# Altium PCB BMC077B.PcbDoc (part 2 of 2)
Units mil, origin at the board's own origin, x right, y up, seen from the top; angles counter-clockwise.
Board outline 3180 x 2450 mil, 4 copper layers (Top Layer, Signal Layer 1, Signal Layer 2, Bottom Layer), stack 61.2 mil thick; 102 components, 30 nets, 186 pads, 124 vias.
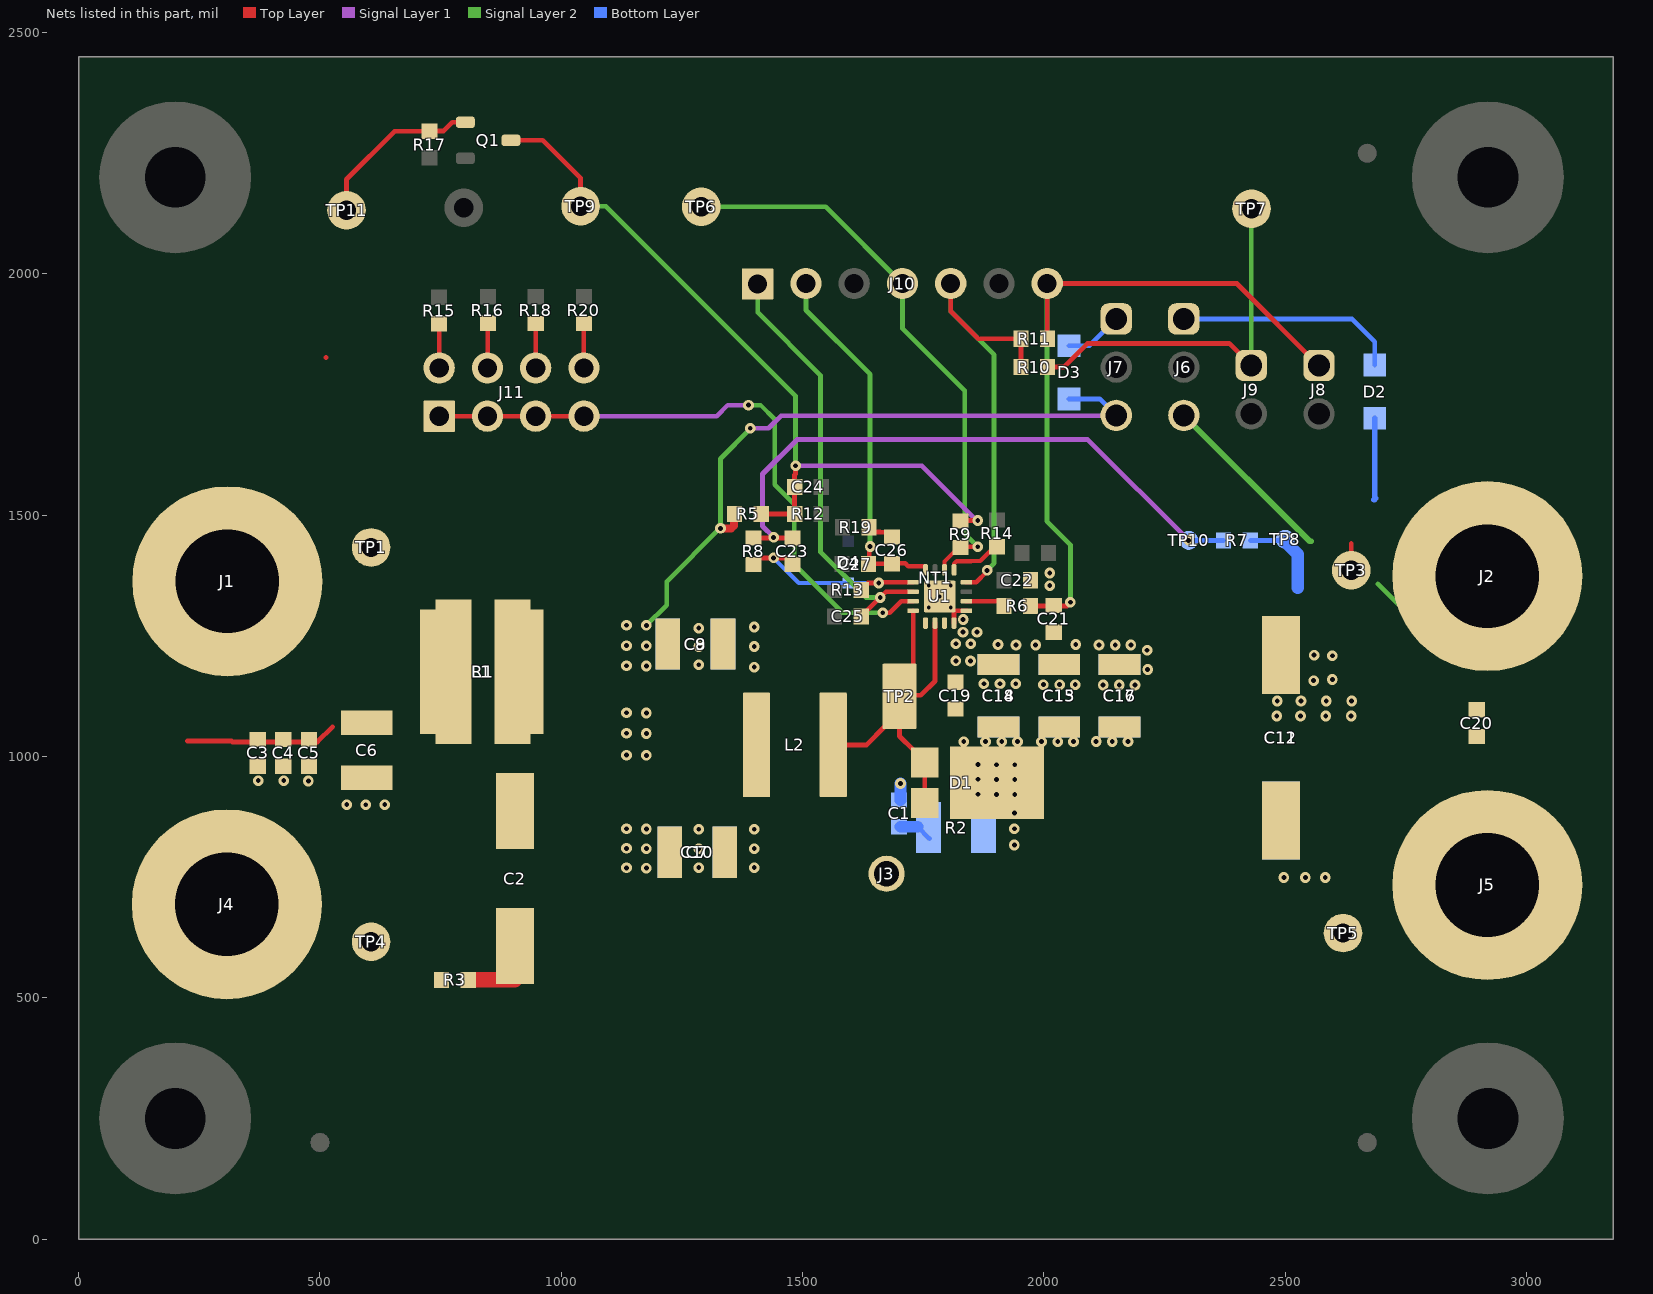
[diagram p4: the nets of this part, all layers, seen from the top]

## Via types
v1: diameter 22, hole 10, Top Layer to Bottom Layer, tented both sides, 119 vias
v2: diameter 19.68, hole 7.87, Top Layer to Bottom Layer, 5 vias

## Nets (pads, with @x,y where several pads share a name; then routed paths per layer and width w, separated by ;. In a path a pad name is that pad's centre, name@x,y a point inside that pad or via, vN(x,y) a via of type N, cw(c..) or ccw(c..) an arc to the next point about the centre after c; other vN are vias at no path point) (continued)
COMP: C26.1 C27.1 J10.2 U1.8 | length 764.9
  Top Layer w9: v1@1639,1441 v1@1640,1440 ; v1(1640,1435) 1638.33,1433.33 1638.33,1400.39 C27.1@1636.56,1398.61 1637.41,1399.47 C26.1@1685,1399.47 ; C26.1@1687.91,1400.35 1712.65,1400.35 1719.15,1393.85 1754.56,1393.85 1754.79,1393.63 U1.8@1754.79,1386.54
  Signal Layer 2 w10: J10.2@1506.98,1980 1506.98,1925.02 1640,1792 v1(1640,1435)
FB: C23.2 D4.1 R8.1 R13.2 U1.9 | length 445.7
  Top Layer w9: v1(1657.73,1359.33) 1659.35,1360.95 U1.9@1729.2,1360.95
  Top Layer w10: R8.1@1398,1397.66 1411.74,1411.4 v1(1440,1411.4) 1464.84,1411.4 C23.2@1478.8,1397.44 ; R13.2@1621.54,1345.2 1635.67,1359.33 v1(1657.73,1359.33)
  Bottom Layer w9: v1(1440,1411.4) 1491.96,1359.44 D4.1@1595,1359.44 1595.11,1359.33 v1(1657.73,1359.33)
MODE: J11.1 J11.3 J11.5 J11.7 U1.11 | length 1332.2
  Top Layer w9: J11.1@747,1705 J11.3@847,1705 J11.5@947,1705 J11.7@1047,1705 ; v1(1666,1297.63) 1680.63,1297.63 1704.58,1321.58 U1.11@1729.2,1321.58
  Signal Layer 1 w9: J11.7@1047,1705 1322,1705 1345,1728 v1(1388,1728)
  Signal Layer 2 w9: v1(1388,1728) 1412.82,1728 1442.17,1698.65 1442.17,1562.83 1482.62,1522.38 1482.62,1398.18 1583.17,1297.63 v1(1666,1297.63)
NetC1_1: C1.1 R2.1 | length 70
  Bottom Layer w10: R2.1@1738.47,854.07 R2.1@1762.91,829.63
  Bottom Layer w24: C1.1@1703,854.07 R2.1@1738.47,854.07
NetC1_2: C1.2 D1.1 D1.2 L2.2 TP2.1 U1.12 U1.13 U1.14 | length 861.7
  Top Layer w10: L2.2@1563.53,1024 1632.73,1024 1670.84,1062.11 TP2.1@1700.88,1092.15 ; TP2.1@1729.2,1114.72 1729.2,1116.44 1720.11,1116.44 TP2.1@1711.92,1124.63 ; U1.12@1729.2,1301.9 1729.2,1185.43 1700.88,1157.11 TP2.1@1700.88,1124.63 ; D1.1@1753.1,903.59 D1.2@1753.1,987.45 1753.1,990.6 1729.76,1013.94 1729.04,1013.94 1700.88,1042.11 TP2.1@1700.88,1092.15 ; U1.14@1774.47,1276.31 1774.47,1156.16 1745.06,1126.75 1714.04,1126.75 TP2.1@1711.92,1124.63 ; TP2.1@1700.88,1092.15 1700.88,1099.3 1700.88,1110.49 TP2.1@1700.88,1124.63 ; TP2.1@1700.88,1124.63 TP2.1@1711.92,1124.63
  Bottom Layer w24: C1.2@1703,909.19 v1(1703,944)
NetC2_2: C2.2 R3.2 | length 166.6
  Top Layer w24: C2.2@903.64,537 C2.2@903.64,580.38 ; C2.2@903.64,601.38 C2.2@903.64,607.24 C2.2@903.64,628.24
  Top Layer w32: R3.2@807.25,537 C2.2@903.64,537
NetC3_1: C3.1 C4.1 C5.1 C6.1 J1.1 L1.1 R1.1 TP1.1 | length 315
  Top Layer w10: 225,1032 316.38,1032 317.52,1030.86 318.35,1030.03 384.45,1030.03 494.68,1030.03 526.18,1061.53
NetC23_1: C23.1 R7.1 R8.2 TP10.1 | length 1293.1
  Top Layer w10: R8.2@1398,1452.77 1440,1452.66 C23.1@1478.8,1452.56
  Signal Layer 1 w10: v1(1440,1454) 1417,1477 1417,1585.2 1488.47,1656.67 2091.01,1656.67 v1(2300,1447.68)
  Bottom Layer w10: v1(2300,1447.68) R7.1@2372.44,1447.68
NetC26_2: C26.2 R19.2 | length 54.3
  Top Layer w10: R19.2@1643.41,1476.15 1643.41,1469.77 1648.31,1464.87 1661.13,1464.87 1661.36,1464.64 1674.95,1464.64 C26.2@1685,1454.59
NetD2_1: D2.1 J6.1 | length 463.5
  Bottom Layer w10: J6.1@2290,1906.67 2638.33,1906.67 2685.71,1859.29 D2.1@2685.71,1811.12
NetD3_1: D3.1 J7.1 | length 121.2
  Signal Layer 1 w10: J7.1@2149.73,1906.94 J7.1@2150,1906.67
  Bottom Layer w10: D3.1@2052.24,1850.97 2094.3,1850.97 J7.1@2150,1906.67
NetJ11_2: J11.2 R15.1 | length 91.4
  Top Layer w9.4: J11.2@747,1805 R15.1@747,1896.44
NetJ11_4: J11.4 R16.2 | length 92.9
  Top Layer w9.4: J11.4@847,1805 848,1806 R16.2@848,1897.44
NetJ11_6: J11.6 R18.2 | length 92.3
  Top Layer w9.4: J11.6@947,1805 R18.2@947,1897.25
NetJ11_8: J11.8 R20.2 | length 92.3
  Top Layer w9.4: J11.8@1047,1805 R20.2@1047,1897.25
NetQ1_1: Q1.1 R17.2 TP11.1 | length 359
  Top Layer w10: TP11.1@555,2132 555,2195.83 654.73,2295.56 R17.2@727,2295.56 727.49,2296.05 756.05,2296.05 774.12,2314.12 Q1.1@801.19,2314.12
NetR6_2: R6.2 U1.2 | length 82
  Top Layer w9: U1.2@1839.43,1321.58 1907.91,1321.58 R6.2@1917.44,1312.05
NetR14_2: R14.2 U1.5 | length 116.5
  Top Layer w9: U1.5@1813.84,1386.54 1813.84,1399.13 1819.47,1404.76 1848.86,1404.76 1848.93,1404.83 1868,1404.83 1897.87,1434.69 R14.2@1903,1434.69
PGND: C3.2 C4.2 C5.2 C6.2 C7.2 C8.2 C9.2 C10.2 C11.2 C12.2 C13.2 C14.2 C15.2 C16.2 C17.2 C18.2 C19.2 C20.2 C21.1 C22.2 J3.1 J4.1 J5.1 NT1.1 R3.1 TP4.1 TP5.1 U1.1 U1.15 U1.16 U1.17 | length 93.2
  Top Layer w10: 512.6,1826.93 512.77,1827.1 ; v2(1784.32,1331.42) v2(1807.15,1308.59) U1.17@1813.84,1301.9 ; U1.16@1813.84,1276.31 U1.17@1813.84,1301.9 ; U1.1@1839.43,1301.9 U1.17@1813.84,1301.9
  other v1: 2497.34,749.26 2541.83,749.26 2583.13,749.26 1285,769.63 1399.95,769.63 1285,808.44 1399.95,808.93 1285,849.28 1399.95,849.28 555.63,900.2 595,900 634.37,900.2 476,949 372,950 425,950 2122.69,1148 2156.23,1148 2188.84,1148 1999,1148.82 2032.54,1148.82 2065.16,1148.82 1875.63,1150.56 1909.17,1150.56 1941.79,1150.56 2215,1180.13 1399.95,1185 1285,1190 1817.63,1198 1848,1197.69 2214,1220 1285,1227.81 1399.95,1227.81 1942.18,1231 1982.8,1231 2114.26,1231 2147.81,1231 2180.42,1231 1905,1232 2066.16,1232 1817.63,1233.63 1848.49,1233.63 1832.52,1257.63 1861.51,1257.63 1285,1265.83 1399.95,1268.27 1832.6,1283.81 2012.02,1354.07 2012.02,1380
  other v2: 1761.48,1308.59 1761.48,1354.26 1807.15,1354.26
PGOOD: J10.5 R10.1 R11.1 U1.4 | length 977.8
  Top Layer w9: U1.4@1839.43,1360.95 1860,1360.95 1882.33,1383.28 v1(1882.33,1385.61)
  Top Layer w10: J10.5@1806.98,1980 1806.98,1922.14 1863.62,1865.5 R11.1@1952.44,1865.5 R10.1@1952.44,1806.67
  Signal Layer 2 w10: J10.5@1806.98,1980 1806.98,1922.14 1897,1832.12 1897,1400.28 v1(1882.33,1385.61)
SS: C25.1 J10.1 U1.10 | length 900.8
  Top Layer w9: v1(1660.91,1329.46) 1672.72,1341.27 U1.10@1729.2,1341.27
  Top Layer w10: C25.1@1621.54,1290.09 v1(1660.91,1329.46)
  Signal Layer 2 w10: J10.1@1406.98,1979 1406.98,1920 1536.98,1790 1536.98,1423.93 1631.45,1329.46 v1(1660.91,1329.46)
SYNC: J10.4 R9.2 TP6.1 U1.6 | length 1196.3
  Top Layer w9: U1.6@1794.16,1386.54 1794.16,1404.01 1823.02,1432.88 R9.2@1827,1432.88 1828.44,1434.32 v1(1863,1434.32)
  Top Layer w10: J10.4@1706.98,1980 J10.4@1710,1983.02
  Signal Layer 2 w10: TP6.1@1290,2139 1547.98,2139 J10.4@1706.98,1980 1706.98,1887.02 1714,1880 1836,1758 1836,1461.32 v1(1863,1434.32)
UVLO: C24.1 Q1.3 R5.1 R9.1 R12.2 TP9.1 | length 1617.2
  Top Layer w10: Q1.3@895.68,2276.72 961.58,2276.72 1040,2198.3 TP9.1@1040,2140 ; R5.1@1414.76,1502.4 R12.2@1483.75,1502.4 1483,1503.15 1483,1583 1485.55,1585.55 v1(1485.55,1602.5) ; R9.1@1827,1488 1827.82,1488.81 v1(1863,1488.81)
  Signal Layer 1 w10: v1(1485.55,1602.5) 1747.31,1602.5 v1@1861,1488.81
  Signal Layer 2 w10: TP9.1@1040,2140 1092.36,2140 1485.55,1746.81 v1(1485.55,1602.5)
VAUX: J9.1 R10.2 TP7.1 | length 786.8
  Top Layer w10: R10.2@2007.56,1806.67 2041.42,1806.67 2090.6,1855.84 2383.9,1855.84 J9.1@2429.74,1810
  Signal Layer 2 w10: J9.1@2429.74,1810 2429.74,2134.4 TP7.1@2430.34,2135
VCC: C21.2 J8.1 J10.7 R6.1 R11.2 | length 1521.7
  Top Layer w10: R6.1@1972.56,1312.05 2047.6,1312.05 v1(2055,1319.45) ; R11.2@2007.56,1865.5 2006.98,1866.08 J10.7@2006.98,1980 2400,1980 J8.1@2570,1810
  Signal Layer 2 w10: J10.7@2006.98,1980 2006.2,1979.22 2006.2,1487.58 2055,1438.78 v1(2055,1319.45)
  Bottom Layer w10: J8.1@2570,1810 J8.1@2574.88,1814.88
VIN: C2.1 C7.1 C8.1 C9.1 C10.1 D3.2 J7.3 L1.2 L2.1 R1.2 R5.2 | length 1434.4
  Top Layer w16: v1(1330,1472.44) 1352.32,1472.44 1358.15,1478.27 R5.2@1358.15,1502.4
  Signal Layer 1 w10: v1(1391.7,1680) 1429.42,1680 1455.42,1706 2149.33,1706 J7.3@2150,1706.67
  Signal Layer 2 w10: v1(1176.42,1271.48) 1218.51,1313.57 1218.51,1362.29 1328.66,1472.44 v1(1330,1472.44) 1330,1616.87 1391.7,1678.57 v1(1391.7,1680)
  Bottom Layer w10: D3.2@2052.24,1740.74 2115.93,1740.74 J7.3@2150,1706.67
  other v1: 1135.13,769.13 1176.42,768.62 1135.13,809.44 1176.42,808.93 1135.13,850.11 1176.42,849.59 1176.42,1002.18 1135.13,1002.7 1176.42,1047.45 1135.13,1047.96 1176.42,1090.01 1135.13,1090.53 1176.42,1187.37 1135.13,1187.89 1176.42,1229.17 1135.13,1229.68 1135.13,1272
VOUT: C11.1 C12.1 C13.1 C14.1 C15.1 C16.1 C17.1 C18.1 C19.1 C20.1 D1.3 D2.2 J2.1 J6.3 R2.2 R7.2 TP3.1 TP8.1 | length 975.3
  Top Layer w10: TP3.1@2637,1385.61 2637,1441.22
  Signal Layer 2 w10: 2692,1357.42 J2.1@2798.71,1250.72
  Signal Layer 2 w12: J6.3@2290,1706.67 2550.94,1445.73 2553.86,1445.73
  Bottom Layer w10: v1@1859.59,980.45 v1@1863.73,980.45 ; R7.2@2427.56,1447.68 2497.68,1447.68 TP8.1@2500,1450 ; J2.1@2771.65,1277.77 J2.1@2798.71,1250.72
  Bottom Layer w12: 2684,1532 2684.43,1532 2687.43,1535 2685.71,1536.72 D2.2@2685.71,1700.88
  Bottom Layer w26: TP8.1@2497.68,1447.68 2526,1419.36 2526,1349.63
  other v1: 1939,816.46 1939,850 1939,882.62 1901.9,920.94 1939.52,920.94 1863.73,921.71 1901.9,952.09 1939.52,952.09 1863.73,952.87 1863.73,983.45 1901.9,982.68 1939.52,982.68 1834,1030.63 1879.13,1030.63 1912.68,1030.63 1945.29,1030.63 1995.18,1030.63 2028.72,1030.63 2061.34,1030.63 2108.18,1030.98 2141.72,1030.98 2174.34,1030.98 2482.44,1083.74 2531.69,1083.74 2584.03,1083.74 2636.74,1083.74 2483.48,1114.89 2532.72,1114.89 2585.06,1114.89 2637.77,1114.89 2558.92,1157.18 2597.85,1159.48 2597.85,1208.72 2560,1209.89
pads on no net: FID1.1 FID2.1 FID3.1 FID4.1 FID5.1 FID6.1 H1.1 H2.1 H3.1 H4.1 H5.0 H6.0 H7.0 H8.0 LBL1.0

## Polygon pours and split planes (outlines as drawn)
VIN on Bottom Layer "BOTTOM_LAYER_VIN_P253" (solid, remove dead copper, pour order 253): 1099.74,1297.63 1232,1297.63 1232,715 1098.35,715
VOUT on Bottom Layer "BOTTOM_LAYER_VOUT_P254" (solid, remove dead copper, pour order 254): 1822,1068 2210,1068 2210,693 1822,693
VOUT on Bottom Layer "BOTTOM_LAYER_VOUT_P255" (solid, remove dead copper, pour order 255): 3150,1061 2447.24,1061 2447.24,1417.87 2617.87,1588.5 3150,1588.5
PGND on Bottom Layer "BOTTOM_LAYER_PGND_P258" (solid, pour order 258): 0,0 3180,0 3180,2450 0,2450
PGND on Top Layer "TOP_LAYER_PGND_P241" (solid, remove dead copper, pour order 241): 1798,1129.63 1798,1317.63 1871.35,1317.63 1922.67,1266.3 2221.61,1266.3 2221.61,1129.63
VOUT on Top Layer "TOP_LAYER_VOUT_P244" (solid, remove dead copper, pour order 244): 1798,1125.59 2215,1125.59 2215,651 1798,651
VIN on Top Layer "TOP_LAYER_VIN_P245" (solid, remove dead copper, pour order 245): 899.53,1361.53 1226.32,1361.53 1262,1325.85 1262,1177 1307,1132 1433.95,1132 1433.95,907.95 1314.95,907.95 1262,855 1262,704.41 1227.59,670 998,670 861.2,806.8 861.2,1323.2
VOUT on Top Layer "TOP_LAYER_VOUT_P246" (solid, remove dead copper, pour order 246): 3156,1096.56 3156,1078.2 2860,1078.2 2841.8,1060 2447.97,1060 2447.97,1337.6 2707.37,1597 3156,1597
NetC3_1 on Top Layer "TOP_LAYER_NETC3_1_P247" (solid, remove dead copper, pour order 247): 822.31,1006.63 0,1006.63 0,1612.54 629.09,1612.54 822.31,1419.32
PGND on Top Layer "TOP_LAYER_PGND_P248" (solid, pour order 248): 0,0 3184,0 3184,2450 0,2450
AGND on Top Layer "Top Layer-AGND" (solid, pour order 242): 1931,1406 1784.69,1406 1784.69,1378.31 1763.06,1378.31 1763.06,1406 1710,1406 1710,1431.37 1639.37,1502 1611.15,1502 1602,1492.85 1602,1293 1583.34,1274.34 1511.4,1274.34 1511.4,1580.4 1547,1616 1882.52,1616 1931,1567.52
NetC1_2 on Top Layer "TOP_LAYER_NETC1_2_P243" (solid, remove dead copper, pour order 243): 1714.65,1310.63 1787.6,1310.63 1787.6,860.35 1589.44,860.35 1534.38,915.66 1535.63,1180.98 1618.66,1263.63 1667.65,1263.63
VOUT on Signal Layer 2 "SIGNAL_LAYER_2_VOUT_P250" (solid, remove dead copper, pour order 250): 1798,1116.49 2207,1116.49 2207,652 1798,652
VOUT on Signal Layer 2 "SIGNAL_LAYER_2_VOUT_P251" (solid, remove dead copper, pour order 251): 3152,1005.1 2560.1,1005.1 2207,652 2130,652 2130,1051.65 2674.56,1596.21 3152,1596.21
PGND on Signal Layer 2 "SIGNAL_LAYER_2_PGND_P257" (solid, pour order 257): 0,0 3180,0 3180,2450 0,2450
PGND on Signal Layer 1 "SIGNAL_LAYER_1_PGND_P249" (solid, pour order 249): 1.72,-13.05 3181.72,-13.05 3181.72,2436.95 1.72,2436.95

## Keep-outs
Keep-Out Layer:
  the board outline again, w10
  text ".Layer_Name" at 577,-902.49 h60

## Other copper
Top Layer:
  pour cut-out: 849.07,1001.89 823.85,1001.44 823.85,1341.99 850.84,1341.99
  pour cut-out: 1536.29,890.29 1433.95,890.29 1433.95,1158.08 1535.71,1158.08
  text ".Layer_Name" at 577,-902.49 h60
Signal Layer 1:
  text ".Layer_Name" at 580.71,-900.3 h60
Signal Layer 2:
  text ".Layer_Name" at 580.71,-900.3 h60
Bottom Layer:
  text ".Layer_Name" at 577,-902.49 h60

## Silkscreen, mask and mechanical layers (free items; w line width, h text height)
Top Overlay:
  lines w10: 1426.98,1556.5 1446.69,1537.77 ; 1433.04,1537.77 1446.69,1537.77 ; 1446.69,1552.93 1446.69,1537.77 ; 1154,651 2236,651 2236,2063.63 1154,2063.63 1154,651
  text "UVLO" at 958.09,2207.82 h70
  text "SYNC" at 1213.12,2204.65 h70
  text "SD" at 514,2200 h70
  text "Vaux" at 2352.76,2200.49 h72.83
  text "SYNC" at 1728.4,2085 h72.83 r90
  text "SS" at 1425.87,2080 h72.83 r90
  text "COMP" at 1531.98,2080 h72.83 r90
  text "AGND" at 1635.32,2080 h72.83 r90
  text "PGOOD" at 1821.99,2080 h72.83 r90
  text "BIAS IC" at 1927.47,2080 h72.83 r90
  text "VCC" at 2034.15,2080 h72.83 r90
  text "AGND" at 690,2010 h70
  text "MODE" at 526.18,1753 h40
  text "VIN+" at 248,1639 h40
  text "VOUT+" at 2930,1605 h40
  text "NN" at 764,1564.71 h40 r90
  text "HS" at 866,1564.71 h40 r90
  text "HN" at 966,1563 h40 r90
  text "NS" at 1067.67,1563 h40 r90
  text "Vin-Bias" at 2173.09,1401.3 h72.83 r90
  text "Vout-Bias" at 2315.85,1355.64 h72.83 r90
  text "Vaux-Bias" at 2443.34,1355 h72.83 r90
  text "VCC-Bias" at 2546,1355 h72.83 r90
  text "GND" at 2975,465 h40
  text "GND" at 243.7,420 h40
  text "LM5157/51571 EVM BOOST" at 1451.48,185 h80
  text ".PRJ_Number" at 1855,115 h80
  text ".PCB_Rev" at 2135.03,115 h80
  text ".Layer_Name" at 577,-902.49 h60
Bottom Overlay:
  text "TP7" at 2399.81,2056 h40
  text "TP11" at 615,2014.19 h40
  text "TP10" at 865,2010 h40
  text "VIN+" at 378,1639 h40
  text "VOUT+" at 3115,1605 h40
  text "J3" at 1609.2,736 h40
  text "GND" at 3080,465 h40
  text "GND" at 369.3,419 h40
  text ".Layer_Name" at 577,-902.49 h60
Top Paste:
  text ".Layer_Name" at 577,-902.49 h60
Bottom Paste:
  text ".Layer_Name" at 577,-902.49 h60
Top Solder:
  text ".Layer_Name" at 577,-902.49 h60
  text ".Layer_Name" at 577,-902.49 h60
Bottom Solder:
  rectangle: 1719,1272 1848,1390.47
  text ".Layer_Name" at 577,-902.49 h60
Drill Guide:
  text ".Layer_Name" at 577,-902.49 h60
M1 Board Outline:
  the board outline again, w10
  text ".Layer_Name" at 577,-902.49 h60
M2 Board Dimensions:
  rectangle: 0,-319 125,-194
  rectangle: 125,-444 500,-319
  lines w7: 0,-319 1000,-319 ; 125,-444 125,-194 ; 250,-444 250,-194 ; 500,-444 500,-194 ; 750,-444 750,-194 ; 0,-444 1000,-444 1000,-194 0,-194 0,-444
  text ".Layer_Name" at 577,-902.49 h60
M3 3D STEP Top:
  text ".Layer_Name" at 577,-902.49 h60
M4 3D STEP Bottom:
  text ".Layer_Name" at 577,-902.49 h60
M5 Assembly Top:
  lines w10: -292,-974.17 6308,-974.17 ; -292,-770.83 6310,-770.83 ; -292,-567.5 -292,-1177.5 3713,-1177.5 6310,-1177.5 6310,-567.5 -291.5,-567.5 -291.5,-1177.5 1284,-1177.5 ; 2173,-1177.5 2173,-567.5 ; 3440,-770.83 3440,-567.5 ; 4280,-770.83 4280,-567.5 ; 4902,-1184 4902,-981.17
  text "COMPONENTS MARKED 'DNP' SHOULD NOT BE POPULATED." at 1153.5,-362.5 h60
  text "ASSEMBLY VARIANT:" at 1153,-478 h60
  text ".VariantName" at 2189,-478 h60
  text "PCB VIEWED FROM TOP SIDE" at -228.5,-699.67 h60
  text "BOARD #:" at 2248,-699.67 h60
  text ".PRJ_Number" at 2793.5,-699.67 h60
  text "REV:" at 3638,-699.67 h60
  text ".PCB_Rev" at 3929.5,-699.67 h60
  text "SVN REV:" at 4476,-699.67 h60
  text ".VersionControl_RevNumber" at 4982,-699.67 h60
  text "TID #:" at 2248,-903 h60
  text ".TID" at 2793.5,-903 h60
  text "PLOT NAME =" at -228.5,-1108.34 h60
  text ".plot_File_Name" at 577,-1108.34 h60
  text "GENERATED    :" at 2250,-1108.34 h60
  text ".Print_Date" at 3119.5,-1108.34 h60
  text ".Print_Time" at 3848.5,-1108.34 h60
  text "TEXAS INSTRUMENTS" at 5113,-1108.34 h60
M6 Assembly Bottom:
  lines w10: -292.5,-771.33 6309.5,-771.33 ; -290.5,-974.67 6309.5,-974.67 ; 1115.5,-1184.5 1115.5,-981.67 ; 1737.5,-771.33 1737.5,-568 ; 2577.5,-771.33 2577.5,-568 ; 3844.5,-1178 3844.5,-568 ; 4733.5,-1178 6309,-1178 6309,-568 -292.5,-568 -292.5,-1178 2304.5,-1178 6309.5,-1178 6309.5,-568
  text "COMPONENTS MARKED 'DNP' SHOULD NOT BE POPULATED." at 6102,-362 h60
  text ".VariantName" at 5058,-478 h60
  text "ASSEMBLY VARIANT:" at 6097,-478 h60
  text ".VersionControl_RevNumber" at 1035.5,-700.17 h60
  text "SVN REV:" at 1541.5,-700.17 h60
  text ".PCB_Rev" at 2088,-700.17 h60
  text "REV:" at 2379.5,-700.17 h60
  text ".PRJ_Number" at 3224,-700.17 h60
  text "BOARD #:" at 3769.5,-700.17 h60
  text "PCB VIEWED FROM BOTTOM SIDE" at 6246,-700.17 h60
  text ".TID" at 3224,-903.5 h60
  text "TID #:" at 3769.5,-903.5 h60
  text "TEXAS INSTRUMENTS" at 904.5,-1108.84 h60
  text ".Print_Time" at 2169,-1108.84 h60
  text ".Print_Date" at 2898,-1108.84 h60
  text "GENERATED    :" at 3767.5,-1108.84 h60
  text ".plot_File_Name" at 5440.5,-1108.84 h60
  text "PLOT NAME =" at 6246,-1108.84 h60
M9 Title Sheet:
  lines w10: -491.5,997.5 -291.5,997.5 ; -491.5,3372.5 -291.5,3372.5 ; -491.5,5747.5 -291.5,5747.5 ; 2008.5,-1377.5 2008.5,-1177.5 ; 2008.5,7922.5 2008.5,8122.5 ; 4508.5,-1377.5 4508.5,-1177.5 ; 4508.5,7922.5 4508.5,8122.5 ; 6321,-1177.5 6321,-567.5 11303.5,-567.5 ; 7008.5,-1377.5 7008.5,-1177.5 ; 7008.5,7922.5 7008.5,8122.5 ; 9508.5,-1377.5 9508.5,-1177.5 ; 9508.5,7922.5 9508.5,8122.5 ; 11303.5,-1177.5 11303.5,-567.5 ; 11303.5,-867.5 14303.5,-867.5 ; 11303.5,-267.5 14303.5,-267.5 ; 11304.5,326.5 14304.5,326.5 ; 12008.5,-1377.5 12008.5,-1177.5 ; 12008.5,7922.5 12008.5,8122.5 ; 12808.5,-1167.5 12808.5,-567.5 ; 14303.5,-567.5 11303.5,-567.5 ; 14303.5,32.5 11303.5,32.5 ; 14308.5,22.5 14308.5,-1177.5 ; 14308.5,827 11304.5,827 11303.5,827 11303.5,326.5 11303.5,32.5 ; 14308.5,997.5 14508.5,997.5 ; 14308.5,3372.5 14508.5,3372.5 ; 14308.5,5747.5 14508.5,5747.5 ; 11303.5,-567.5 11303.5,32.5 ; 14308.5,-1177.5 14308.5,7922.5 -291.5,7922.5 -291.5,-1177.5 14308.5,-1177.5 ; -491.5,-1377.5 -491.5,8122.5 14508.5,8122.5 14508.5,-1377.5 -491.5,-1377.5
  text "1" at 739.84,7992.5 h70
  text "2" at 3235.5,7992.5 h70
  text "3" at 5724.84,7992.5 h70
  text "4" at 8231.51,7992.5 h70
  text "5" at 10730.5,7992.5 h70
  text "6" at 13235.5,7992.5 h70
  text "A" at -416.5,6849.5 h70
  text "A" at 14383.5,6849.5 h70
  text "B" at -416.5,4469.5 h70
  text "B" at 14383.5,4469.5 h70
  text "C" at -416.5,2094.5 h70
  text "C" at 14383.5,2094.5 h70
  text "PROJECT TITLE:" at 11343.5,233.5 h45
  text ".PRJ_Title" at 11393.5,100.17 h70
  text "DESIGNED FOR:" at 11343.5,-67.5 h45
  text ".PRJ_Customer" at 11393.5,-207.5 h70
  text "D" at -416.5,-275.5 h70
  text "D" at 14383.5,-275.5 h70
  text "FILE NAME:" at 11343.5,-367.5 h45
  text ".PCB_File_Name_No_Path" at 11393.5,-487.5 h70
  text "ENGINEER:" at 11343.5,-657.5 h45
  text "LAYOUT BY:" at 12848.5,-657.5 h45
  text ".PRJ_Engineer" at 11393.5,-812.49 h70
  text ".PCB_Layout" at 12899,-812.49 h70
  text ".Layer_Name" at 577,-902.49 h60
  text "ALTIUM DESIGNER VERSION:" at 12848.5,-967.5 h45
  text ".print_Scale" at 11393.5,-1100.83 h70
  text ".Application_BuildNumber" at 12899,-1100.83 h70
  text "1" at 739.84,-1307.5 h70
  text "2" at 3235.5,-1307.5 h70
  text "3" at 5724.84,-1307.5 h70
  text "4" at 8231.51,-1307.5 h70
  text "5" at 10730.5,-1307.5 h70
  text "6" at 13235.5,-1307.5 h70
M10 Fab Notes:
  drawing of 189 lines, arcs and shapes, not listed
  text "DESIGN INFORMATION" at 12382.02,6312.17 h60
  text "MIN. TRACK WIDTH:" at 11737.46,6180.05 h60
  text "9" at 12833.7,6180.05 h60
  text "MIL" at 12988.46,6180.05 h60
  text "MIN. CLEARANCE:" at 11737.46,6055.92 h60
  text "0.2" at 12773.7,6055.93 h60
  text "mm" at 12988.46,6055.92 h60
  text "MIN. VIA PAD SIZE:" at 11737.46,5931.8 h60
  text "MIL" at 12988.46,5931.8 h60
  text "19.685" at 12620,5928 h60
  text "0.05mm (2MIL)" at 12432.46,5801.9 h60
  text "MINIMUM ANNULAR RING" at 11408.23,5793.67 h60
  text "EXTERNAL" at 13140.46,5793.67 h60
  text "PER" at 11608.23,5683.55 h60
  text "IPC-D-275 CLASS 2 LEVEL C" at 11828.23,5683.54 h60
  text "MIL, HOLES" at 13316.46,5583.07 h60
  text "+/-" at 12924,5574.48 h60
  text "+/-" at 13778,5574.48 h60
  text "REGISTRATION TOLERANCES:" at 11408.23,5573.42 h60
  text "METAL" at 12608,5573.42 h60
  text "5" at 13184.2,5573.42 h60
  text "3" at 14017.2,5573.42 h60
  text "MIL" at 14133.46,5573.42 h60
  text "HOLE SIZE TOLERANCE (UNLESS OTHERWISE SPECIFIED):" at 11408.23,5475.1 h60
  text "+/-" at 13778,5472.23 h60
  text "3" at 14017.2,5471.17 h60
  text "MIL" at 14133.46,5471.17 h60
  text "MATERIAL:" at 11333.46,5333.52 h60
  text "FR-4 High Tg" at 12319.9,5205 h60
  text "X" at 12175.46,5197.01 h60
  text "FR-408" at 11754.46,5192.49 h60
  text "OTHER" at 13242.46,5192.49 h60
  text "62 MIL (1.6mm) +/-10%" at 12074.56,5049.46 h60
  text "X" at 11954.46,5047.01 h60
  text "THICKNESS:" at 11408.23,5041.24 h60
  text "OTHER" at 13359.46,5041.24 h60
  text "TOLERANCE:" at 11408.23,4902.92 h60
  text "X" at 12256.46,4902.92 h60
  text "ANSI IPC-6012 TYPE 3 CLASS 2" at 12434.48,4902.92 h60
  text "OTHER +/-" at 12434.46,4758.73 h60
  text "BOW & TWIST:" at 11408.23,4613.54 h60
  text "X" at 12256.46,4613.54 h60
  text "ANSI IPC-6012 TYPE 3 CLASS 2" at 12434.48,4613.54 h60
  text "OTHER +/-" at 12434.46,4466.85 h60
  text "DRILLING:" at 11333.46,4336.23 h60
  text "NC_DRILL FILES" at 13094.46,4231.04 h60
  text "REFERENCE:" at 11408.23,4227.1 h60
  text "X" at 12065.46,4227.01 h60
  text "AS SHOWN" at 12243.46,4227.1 h60
  text "X" at 12966.46,4227.1 h60
  text "OTHER" at 13392.46,4084.85 h60
  text "PTH COPPER THICKNESS:" at 11407.91,4081.32 h60
  text "X" at 12547.14,4081.32 h60
  text "20-30 um" at 12675.14,4081.32 h60
  text "BOARD FINISH:" at 11333.46,3933.73 h60
  text "SILKSCREEN:" at 11488.68,3823.6 h60
  text "X" at 12446.46,3823.6 h60
  text "TOP" at 12563.46,3823.6 h60
  text "X" at 12956.46,3823.6 h60
  text "BOTTOM" at 13074.46,3823.6 h60
  text "SILKSCREEN COLOR:" at 11488.68,3668.41 h60
  text "X" at 12445.46,3668.41 h60
  text "WHITE" at 12563.46,3668.41 h60
  text "OTHER" at 13074.46,3668.41 h60
  text "X" at 12576.46,3524.96 h60
  text "GREEN" at 12694.46,3524.96 h60
  text "OTHER" at 13312.46,3524.96 h60
  text "SOLDER RESIST COLOR:" at 11488.68,3518.1 h60
  text "X" at 12576.46,3370.71 h60
  text "MATTE" at 12694.46,3370.71 h60
  text "SEMI-GLOSS" at 13312,3370.07 h60
  text "IMMERSION GOLD (ENIG)" at 12394.46,3197.94 h60
  text "ENEPIG" at 13732,3190.72 h60
  text "SURFACE FINISH:" at 11333.46,3189.72 h60
  text "X" at 12216.46,3189.72 h60
  text "IMM. TIN/SILVER OR EQUIV" at 11663,3052.4 h60
  text "OTHER" at 13094.46,3048.47 h60
  text "ARRAY/PANEL:" at 11333.46,2893.09 h60
  text "CUT AND TRIM PER M1 BOARD OUTLINE" at 12394.46,2884.87 h60
  text "N.C. ROUTE" at 12394.46,2748.9 h60
  text "X" at 13085,2748.9 h60
  text "V. SCORE" at 13260.46,2748.9 h60
  text "CERTIFICATION:" at 11333.46,2619.77 h60
  text "MATERIALS AND WORKMANSHIP FOR ALL PCBS" at 12058.46,2619.77 h60
  text "TO MEET OR EXCEED THE REQUIREMENTS OF:" at 12058.46,2525.71 h60
  text "X" at 11695.97,2397.08 h60
  text "ANSI IPC-A-600F CLASS ->" at 11823.96,2397.08 h60
  text "X" at 13471.97,2397.08 h60
  text "2" at 13581.96,2397.08 h60
  text "1" at 13266.96,2395.58 h60
  text "3" at 13935.96,2395.58 h60
  text "X" at 12507.97,2249.39 h60
  text "RoHS" at 12635.96,2249.39 h60
  text "OTHER" at 13280.36,2249.39 h60
  text "PER ORDER" at 13677.42,2249.39 h60
  text "ALL BOARDS MUST MEET OR EXCEED UL94-V0 REQUIREMENTS." at 11361,2095.57 h60
  text "PCB MUST BEAR THE UL94V-0 UL REGISTERED MATERIAL ID NUMBER" at 11361,1979.5 h60
  text "ADDITIONAL REQUIREMENTS:" at 11333.46,1810.08 h60
  text "MICROSECTION:" at 11408.23,1702.95 h60
  text "YES" at 12313.96,1702.95 h60
  text "REQUIRED" at 13175.46,1558.62 h60
  text "BARE BOARD ELEC. TEST:" at 11408.23,1555.76 h60
  text "NONE" at 12713.96,1555.76 h60
  text "X" at 13057.46,1555.76 h60
  text "PER ORDER" at 13767.46,1555.76 h60
  text "XX MIL VIAS REQUIRE NON-CONDUCTIVE FILL AND PLANARIZE" at 11576.38,1350.82 h59
  text "XX MIL VIAS REQUIRE CONDUCTIVE FILL AND PLANARIZE" at 11584.38,1246.84 h60
  text "OUTER XX MIL TRACES REQUIRE 50 OHM SINGLE-ENDED IMPEDANCE" at 11583.39,1083.46 h58
  text "LAYER 2 & 3 (INNER LAYERS) XX MIL WIDE, XX MIL SPACE / TRACES REQUIRE 100 OHM DIFFERENTIAL IMPEDANCE" at 11575.39,847.74 h60
  text ".Layer_Name" at 577,-902.49 h60
M11 Gerber Information:
  lines w10: -292,-974.17 6308,-974.17 ; -292,-770.83 6310,-770.83 ; -292,-567.5 -292,-1177.5 3713,-1177.5 6310,-1177.5 6310,-567.5 -291.5,-567.5 -291.5,-1177.5 1284,-1177.5 ; 2173,-1177.5 2173,-567.5 ; 3440,-770.83 3440,-567.5 ; 4280,-770.83 4280,-567.5 ; 4902,-1184 4902,-981.17
  text "ALL ARTWORK VIEWED FROM TOP SIDE" at -228.5,-699.67 h60
  text "BOARD #:" at 2248,-699.67 h60
  text ".PRJ_Number" at 2793.5,-699.67 h60
  text "REV:" at 3638,-699.67 h60
  text ".PCB_Rev" at 3929.5,-699.67 h60
  text "SVN REV:" at 4476,-699.67 h60
  text ".VersionControl_RevNumber" at 4982,-699.67 h60
  text "LAYER NAME =" at -228.5,-902.49 h60
  text "TID #:" at 2248,-903 h60
  text ".TID" at 2793.5,-903 h60
  text "PLOT NAME =" at -228.5,-1108.34 h60
  text ".plot_File_Name" at 577,-1108.34 h60
  text "GENERATED    :" at 2250,-1108.34 h60
  text ".Print_Date" at 3119.5,-1108.34 h60
  text ".Print_Time" at 3848.5,-1108.34 h60
  text "TEXAS INSTRUMENTS" at 5113,-1108.34 h60
M12 Stackup:
  drawing of 295 lines, arcs and shapes, not listed
  text "Layer" at 9821.2,7825 h60
  text "Name" at 10231.11,7825 h60
  text "Material" at 11170.85,7825 h60
  text "Thickness" at 12030.62,7825 h60
  text "Constant" at 12680.46,7825 h60
  text "Board Layer Stack" at 13250.32,7825 h60
  text "Top Overlay" at 10231.11,7705 h60
  text "Top Solder" at 10231.11,7585 h60
  text "Solder Resist" at 11170.85,7585 h60
  text "0.40mil" at 12030.62,7585 h60
  text "3.5" at 12680.46,7585 h60
  text "1" at 9821.2,7465 h60
  text "Top Layer" at 10231.11,7465 h60
  text "2.80mil" at 12030.62,7465 h60
  text "Dielectric1" at 10231.11,7345 h60
  text "FR-4 High Tg" at 11170.85,7345 h60
  text "6.00mil" at 12030.62,7345 h60
  text "4.8" at 12680.46,7345 h60
  text "2" at 9821.2,7225 h60
  text "Signal Layer 1" at 10231.11,7225 h60
  text "2.80mil" at 12030.62,7225 h60
  text "Dielectric 2" at 10231.11,7105 h60
  text "FR-4 High Tg" at 11170.85,7105 h60
  text "38.00mil" at 12030.62,7105 h60
  text "4.2" at 12680.46,7105 h60
  text "3" at 9821.2,6985 h60
  text "Signal Layer 2" at 10231.11,6985 h60
  text "2.80mil" at 12030.62,6985 h60
  text "Dielectric 3" at 10231.11,6865 h60
  text "FR-4 High Tg" at 11170.85,6865 h60
  text "6.00mil" at 12030.62,6865 h60
  text "4.2" at 12680.46,6865 h60
  text "4" at 9821.2,6745 h60
  text "Bottom Layer" at 10231.11,6745 h60
  text "2.80mil" at 12030.62,6745 h60
  text "Bottom Solder" at 10231.11,6625 h60
  text "Solder Resist" at 11170.85,6625 h60
  text "0.40mil" at 12030.62,6625 h60
  text "3.5" at 12680.46,6625 h60
  text "Bottom Overlay" at 10231.11,6505 h60
  text ".Layer_Name" at 577,-902.49 h60
M13 Component Bodies Top:
  text ".Layer_Name" at 577,-902.49 h60
M14 Component Bodies Bottom:
  text ".Layer_Name" at 577,-902.49 h60
M15 Courtyards Top:
  text ".Layer_Name" at 577,-902.49 h60
M16 Courtyards Bottom:
  text ".Layer_Name" at 577,-902.49 h60
Drill Drawing:
  circle w10: c3458.67,1516.18 r27.59
  lines w10: 3431.08,1419.6 3486.26,1419.6 3458.67,1364.41 3431.08,1419.6 ; 3431.08,1626.56 3444.87,1626.56 3458.67,1612.76 3472.47,1626.56 3486.26,1626.56 3472.47,1640.36 3486.26,1654.15 3472.47,1654.15 3458.67,1667.95 3444.87,1654.15 3431.08,1654.15 3444.87,1640.36 3431.08,1626.56 ; 3431.08,1764.53 3458.67,1736.94 3486.26,1764.53 3458.67,1792.13 3431.08,1764.53 ; 3431.08,1861.11 3486.26,1861.11 3486.26,1916.3 3431.08,1916.3 3431.08,1861.11 ; 3431.08,1985.29 3458.67,1999.09 3486.26,1985.29 3472.47,2012.88 3486.26,2040.48 3458.67,2026.68 3431.08,2040.48 3444.87,2012.88 3431.08,1985.29 ; 3431.08,2109.47 3431.08,2123.26 3444.87,2137.06 3431.08,2150.86 3431.08,2164.66 3444.87,2164.66 3458.67,2150.86 3472.47,2164.66 3486.26,2164.66 3486.26,2150.86 3472.47,2137.06 3486.26,2123.26 3486.26,2109.47 3472.47,2109.47 3458.67,2123.26 3444.87,2109.47 3431.08,2109.47 ; 3431.08,2247.44 3444.87,2247.44 3444.87,2233.64 3472.47,2233.64 3472.47,2247.44 3486.26,2247.44 3486.26,2275.03 3472.47,2275.03 3472.47,2288.83 3444.87,2288.83 3444.87,2275.03 3431.08,2275.03 3431.08,2247.44
  lines w12: 3381.04,1327.16 6611.56,1327.16 ; 3381.04,2320.56 6611.56,2320.56 ; 3718.9,1202.98 3718.9,2444.74 ; 4050.9,1202.98 4050.9,2444.74 ; 4687.46,1202.98 4687.46,2444.74 ; 4946.56,1202.98 4946.56,2444.74 ; 5321.72,1202.98 5321.72,2444.74 ; 6045.1,1202.98 6045.1,2444.74 ; 3381.04,1202.98 6611.56,1202.98 6611.56,2444.74 3381.04,2444.74 3381.04,1202.98
  text "Symbol" at 3455.55,2357.82 h72
  text "Quantity" at 3756.15,2357.82 h72
  text "Finished Hole Size" at 4088.16,2357.82 h72
  text "Plated" at 4724.71,2357.82 h72
  text "Hole Type" at 4983.82,2357.82 h72
  text "Drill Layer Pair" at 5358.97,2357.82 h72
  text "Hole Tolerance" at 6082.36,2357.82 h72
  text "5" at 3756.15,2233.64 h60
  text "7.87mil (0.200mm)" at 4088.16,2233.64 h60
  text "PTH" at 4724.71,2233.64 h60
  text "Round" at 4983.82,2233.64 h60
  text "Top Layer - Bottom Layer" at 5358.97,2233.64 h60
  text "119" at 3756.15,2109.47 h60
  text "10.00mil (0.254mm)" at 4088.16,2109.47 h60
  text "PTH" at 4724.71,2109.47 h60
  text "Round" at 4983.82,2109.47 h60
  text "Top Layer - Bottom Layer" at 5358.97,2109.47 h60
  text "7" at 3756.15,1985.29 h60
  text "39.37mil (1.000mm)" at 4088.16,1985.29 h60
  text "PTH" at 4724.71,1985.29 h60
  text "Round" at 4983.82,1985.29 h60
  text "Top Layer - Bottom Layer" at 5358.97,1985.29 h60
  text "17" at 3756.15,1861.11 h60
  text "40.00mil (1.016mm)" at 4088.16,1861.11 h60
  text "PTH" at 4724.71,1861.11 h60
  text "Round" at 4983.82,1861.11 h60
  text "Top Layer - Bottom Layer" at 5358.97,1861.11 h60
  text "10" at 3756.15,1736.94 h60
  text "45.28mil (1.150mm)" at 4088.16,1736.94 h60
  text "PTH" at 4724.71,1736.94 h60
  text "Round" at 4983.82,1736.94 h60
  text "Top Layer - Bottom Layer" at 5358.97,1736.94 h60
  text "1" at 3756.15,1612.76 h60
  text "52.00mil (1.321mm)" at 4088.16,1612.76 h60
  text "PTH" at 4724.71,1612.76 h60
  text "Round" at 4983.82,1612.76 h60
  text "Top Layer - Bottom Layer" at 5358.97,1612.76 h60
  text "4" at 3756.15,1488.59 h60
  text "125.98mil (3.200mm)" at 4088.16,1488.59 h60
  text "PTH" at 4724.71,1488.59 h60
  text "Round" at 4983.82,1488.59 h60
  text "Top Layer - Bottom Layer" at 5358.97,1488.59 h60
  text "4" at 3756.15,1364.41 h60
  text "214.57mil (5.450mm)" at 4088.16,1364.41 h60
  text "PTH" at 4724.71,1364.41 h60
  text "Round" at 4983.82,1364.41 h60
  text "Top Layer - Bottom Layer" at 5358.97,1364.41 h60
  text "167 Total" at 3756.15,1240.23 h60
  text ".Layer_Name" at 577,-902.49 h60
M17 Embedded Cavity:
  text ".Layer_Name" at 577,-902.49 h60
M18 Embedded Assembly:
  text ".Layer_Name" at 577,-902.49 h60
M19 Embedded Keepout:
  text ".Layer_Name" at 577,-902.49 h60

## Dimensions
0,0 to 0,2450 on M2 Board Dimensions
0,0 to 3180,0 on M2 Board Dimensions
0,-444 to 1000,-444 on M2 Board Dimensions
